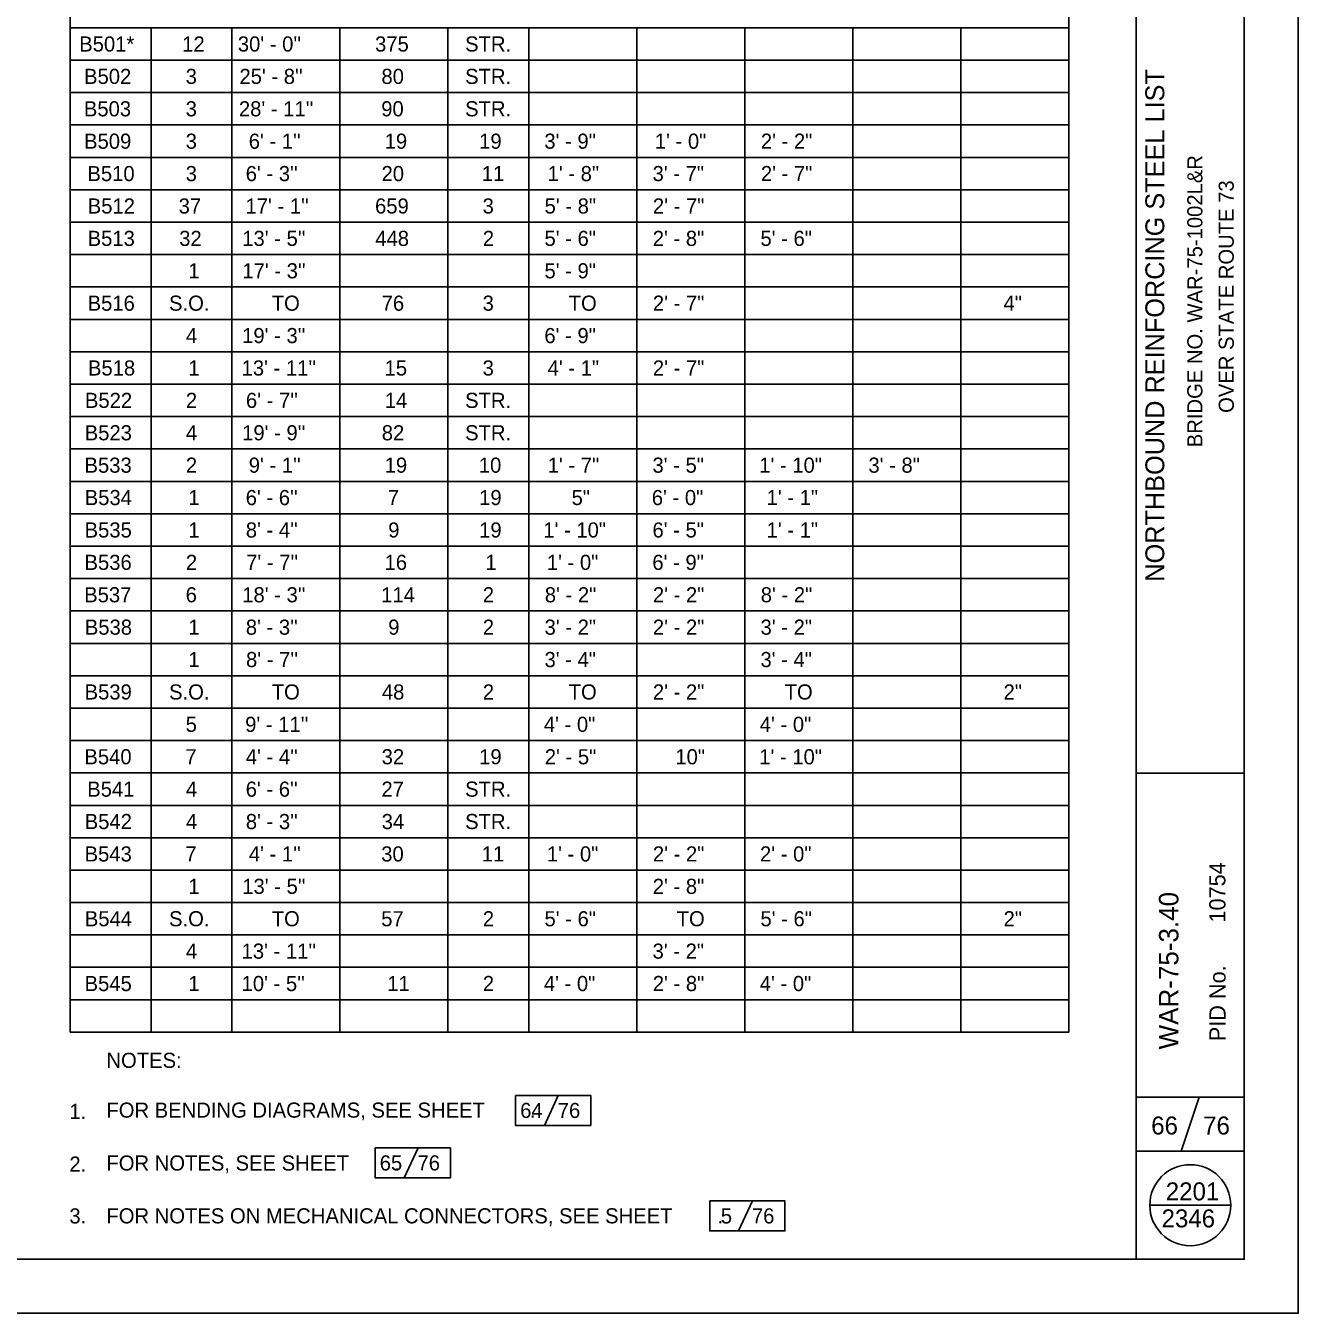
# Model space of a CAD drawing. Extents: x 1485751 to 1485785, y 230696.6 to 230718.6.
# Drawn here: x 1485773.25 to 1485785.03, y 230696.64 to 230708.56 of the extents above; entities that cross this region are included whole.
import ezdxf

# ---------------------------------------------------------------- set-up
doc = ezdxf.new("R2010")
doc.units = 0
for name, color, linetype in [('BR_P_Gen_Text', 7, 'Continuous'), ('BR_P_Sub_Text', 7, 'Continuous'), ('SH_Border', 7, 'Continuous'), ('SH_Cut_Line', 7, 'Continuous'), ('SH_Data', 7, 'Continuous'), ('TX_P_Misc', 7, 'Continuous')]:
    doc.layers.add(name, color=color, linetype=linetype)

msp = doc.modelspace()

# ---------------------------------------------------------------- linework, layer by layer
at = {"layer": 'BR_P_Gen_Text'}
for p, q in [((1485778.18, 230698.658), (1485778.052, 230698.38)), ((1485776.882, 230698.172), (1485776.753, 230697.894)), ((1485779.978, 230697.681), (1485779.85, 230697.403))]:
    msp.add_line(p, q, dxfattribs=at)
for points in [[(1485777.783, 230698.658), (1485778.48, 230698.658), (1485778.48, 230698.38), (1485777.783, 230698.38)], [(1485777.783, 230698.658), (1485778.48, 230698.658), (1485778.48, 230698.38), (1485777.783, 230698.38)], [(1485776.485, 230698.172), (1485777.181, 230698.172), (1485777.181, 230697.894), (1485776.485, 230697.894)], [(1485776.485, 230698.172), (1485777.181, 230698.172), (1485777.181, 230697.894), (1485776.485, 230697.894)], [(1485779.582, 230697.681), (1485780.278, 230697.681), (1485780.278, 230697.403), (1485779.582, 230697.403)], [(1485779.582, 230697.681), (1485780.278, 230697.681), (1485780.278, 230697.403), (1485779.582, 230697.403)]]:
    msp.add_lwpolyline(points, close=True, dxfattribs=at)
at = {"layer": 'SH_Border'}
for p, q in [((1485783.533, 230697.141), (1485783.533, 230718.141)), ((1485783.533, 230697.141), (1485783.533, 230718.141)), ((1485783.533, 230697.141), (1485783.533, 230718.141)), ((1485783.533, 230701.641), (1485784.533, 230701.641)), ((1485783.533, 230701.641), (1485784.533, 230701.641)), ((1485783.533, 230701.641), (1485784.533, 230701.641)), ((1485783.533, 230698.641), (1485784.533, 230698.641)), ((1485783.95, 230698.141), (1485784.116, 230698.641)), ((1485783.533, 230698.141), (1485784.533, 230698.141))]:
    msp.add_line(p, q, dxfattribs=at)
msp.add_lwpolyline([(1485753.033, 230718.141), (1485784.533, 230718.141), (1485784.533, 230697.141), (1485753.033, 230697.141)], close=True, dxfattribs=at)
at = {"layer": 'SH_Cut_Line'}
msp.add_lwpolyline([(1485751.033, 230718.641), (1485785.033, 230718.641), (1485785.033, 230696.641), (1485751.033, 230696.641)], close=True, dxfattribs=at)
at = {"layer": 'SH_Data'}
msp.add_line((1485783.658, 230697.641), (1485784.408, 230697.641), dxfattribs=at)
msp.add_line((1485783.658, 230697.641), (1485784.408, 230697.641), dxfattribs=at)
msp.add_line((1485783.658, 230697.641), (1485784.408, 230697.641), dxfattribs=at)
msp.add_circle((1485784.033, 230697.641), 0.375, dxfattribs=at)
at = {"layer": 'TX_P_Misc'}
for p, q in [((1485773.658, 230717.394), (1485773.658, 230699.244)), ((1485782.908, 230717.394), (1485782.908, 230699.244)), ((1485773.658, 230708.544), (1485782.908, 230708.544)), ((1485774.408, 230708.544), (1485774.408, 230699.244)), ((1485775.158, 230708.544), (1485775.158, 230699.244)), ((1485776.158, 230708.544), (1485776.158, 230699.244)), ((1485777.158, 230708.544), (1485777.158, 230699.244)), ((1485777.908, 230708.544), (1485777.908, 230699.244)), ((1485778.908, 230708.544), (1485778.908, 230699.244)), ((1485779.908, 230708.544), (1485779.908, 230699.244)), ((1485780.908, 230708.544), (1485780.908, 230699.244)), ((1485781.908, 230708.544), (1485781.908, 230699.244)), ((1485773.658, 230708.244), (1485782.908, 230708.244)), ((1485773.658, 230707.944), (1485782.908, 230707.944)), ((1485773.658, 230707.644), (1485782.908, 230707.644)), ((1485773.658, 230707.344), (1485782.908, 230707.344)), ((1485773.658, 230707.044), (1485782.908, 230707.044)), ((1485773.658, 230706.744), (1485782.908, 230706.744)), ((1485773.658, 230706.444), (1485782.908, 230706.444)), ((1485773.658, 230706.144), (1485782.908, 230706.144)), ((1485773.658, 230705.844), (1485782.908, 230705.844)), ((1485773.658, 230705.544), (1485782.908, 230705.544)), ((1485773.658, 230705.244), (1485782.908, 230705.244)), ((1485773.658, 230704.944), (1485782.908, 230704.944)), ((1485773.658, 230704.644), (1485782.908, 230704.644)), ((1485773.658, 230704.344), (1485782.908, 230704.344)), ((1485773.658, 230704.044), (1485782.908, 230704.044)), ((1485773.658, 230703.744), (1485782.908, 230703.744)), ((1485773.658, 230703.444), (1485782.908, 230703.444)), ((1485773.658, 230703.144), (1485782.908, 230703.144)), ((1485773.658, 230702.844), (1485782.908, 230702.844)), ((1485773.658, 230702.544), (1485782.908, 230702.544)), ((1485773.658, 230702.244), (1485782.908, 230702.244)), ((1485773.658, 230701.944), (1485782.908, 230701.944)), ((1485773.658, 230701.644), (1485782.908, 230701.644)), ((1485773.658, 230701.344), (1485782.908, 230701.344)), ((1485773.658, 230701.044), (1485782.908, 230701.044)), ((1485773.658, 230700.744), (1485782.908, 230700.744)), ((1485773.658, 230700.444), (1485782.908, 230700.444)), ((1485773.658, 230700.144), (1485782.908, 230700.144)), ((1485773.658, 230699.844), (1485782.908, 230699.844)), ((1485773.658, 230699.544), (1485782.908, 230699.544)), ((1485773.658, 230699.244), (1485782.908, 230699.244))]:
    msp.add_line(p, q, dxfattribs=at)

# ---------------------------------------------------------------- texts
at = {"layer": 'BR_P_Gen_Text'}
for s, p in [('64', (1485777.827, 230698.449)), ('76', (1485778.175, 230698.449)), ('65', (1485776.526, 230697.963)), ('76', (1485776.876, 230697.963)), ('5', (1485779.685, 230697.472)), ('76', (1485779.973, 230697.472))]:
    msp.add_text(s, height=0.14, dxfattribs=at).set_placement(p)
at = {"layer": 'BR_P_Sub_Text'}
msp.add_text('WAR-75-3.40', height=0.18, rotation=90, dxfattribs=at).set_placement((1485783.923, 230699.084))
at = {"layer": 'SH_Data'}
for s, height, p in [('     NORTHBOUND REINFORCING STEEL LIST    ', 0.175, (1485783.792, 230703.09)), ('BRIDGE NO. WAR-75-1002L&R', 0.14, (1485784.145, 230704.66)), ('OVER STATE ROUTE 73', 0.14, (1485784.436, 230704.978)), ('10754', 0.15, (1485784.358, 230700.259)), ('PID No.', 0.15, (1485784.36, 230699.16))]:
    msp.add_text(s, height=height, rotation=90, dxfattribs=at).set_placement(p)
for s, p in [('66', (1485783.671, 230698.296)), ('76', (1485784.152, 230698.296)), ('2201', (1485783.806, 230697.686)), ('2346', (1485783.767, 230697.436))]:
    msp.add_text(s, height=0.1666, dxfattribs=at).set_placement(p)
at = {"layer": 'TX_P_Misc'}
for s, p in [('B501*', (1485773.743, 230708.324)), ('12', (1485774.697, 230708.324)), ("30' - 0''", (1485775.212, 230708.324)), ('375', (1485776.483, 230708.324)), ('STR.', (1485777.317, 230708.324)), ('B502', (1485773.788, 230708.024)), ('3', (1485774.729, 230708.024)), ("25' - 8''", (1485775.227, 230708.024)), ('80', (1485776.542, 230708.024)), ('STR.', (1485777.317, 230708.024)), ('B503', (1485773.786, 230707.724)), ('3', (1485774.729, 230707.724)), ("28' - 11''", (1485775.222, 230707.724)), ('90', (1485776.54, 230707.724)), ('STR.', (1485777.317, 230707.724)), ('B509', (1485773.788, 230707.424)), ('3', (1485774.729, 230707.424)), ("6' - 1''", (1485775.313, 230707.424)), ('19', (1485776.572, 230707.424)), ('19', (1485777.447, 230707.424)), ('3\' - 9"', (1485778.051, 230707.424)), ('1\' - 0"', (1485779.074, 230707.424)), ('2\' - 2"', (1485780.056, 230707.424)), ('B510', (1485773.819, 230707.124)), ('3', (1485774.729, 230707.124)), ("6' - 3''", (1485775.285, 230707.124)), ('20', (1485776.543, 230707.124)), ('11', (1485777.471, 230707.124)), ('1\' - 8"', (1485778.081, 230707.124)), ('3\' - 7"', (1485779.053, 230707.124)), ('2\' - 7"', (1485780.056, 230707.124)), ('B512', (1485773.822, 230706.824)), ('37', (1485774.664, 230706.824)), ("17' - 1''", (1485775.283, 230706.824)), ('659', (1485776.483, 230706.824)), ('3', (1485777.479, 230706.824)), ('5\' - 8"', (1485778.053, 230706.824)), ('2\' - 7"', (1485779.056, 230706.824)), ('B513', (1485773.821, 230706.524)), ('32', (1485774.669, 230706.524)), ("13' - 5''", (1485775.253, 230706.524)), ('448', (1485776.485, 230706.524)), ('2', (1485777.481, 230706.524)), ('5\' - 6"', (1485778.052, 230706.524)), ('2\' - 8"', (1485779.055, 230706.524)), ('5\' - 6"', (1485780.052, 230706.524)), ('1', (1485774.754, 230706.224)), ("17' - 3''", (1485775.254, 230706.224)), ('5\' - 9"', (1485778.052, 230706.224)), ('B516', (1485773.821, 230705.924)), ('S.O.', (1485774.575, 230705.924)), ('TO', (1485775.526, 230705.924)), ('76', (1485776.544, 230705.924)), ('3', (1485777.479, 230705.924)), ('TO', (1485778.276, 230705.924)), ('2\' - 7"', (1485779.056, 230705.924)), (' 4"', (1485782.251, 230705.924)), ('4', (1485774.731, 230705.624)), ("19' - 3''", (1485775.252, 230705.624)), ('6\' - 9"', (1485778.051, 230705.624)), ('B518', (1485773.824, 230705.324)), ('1', (1485774.754, 230705.324)), ("13' - 11''", (1485775.247, 230705.324)), ('15', (1485776.571, 230705.324)), ('3', (1485777.479, 230705.324)), ('4\' - 1"', (1485778.081, 230705.324)), ('2\' - 7"', (1485779.056, 230705.324)), ('B522', (1485773.796, 230705.024)), ('2', (1485774.731, 230705.024)), ("6' - 7''", (1485775.287, 230705.024)), ('14', (1485776.573, 230705.024)), ('STR.', (1485777.317, 230705.024)), ('B523', (1485773.794, 230704.724)), ('4', (1485774.731, 230704.724)), ("19' - 9''", (1485775.252, 230704.724)), ('82', (1485776.545, 230704.724)), ('STR.', (1485777.317, 230704.724)), ('B533', (1485773.792, 230704.424)), ('2', (1485774.731, 230704.424)), ("9' - 1''", (1485775.313, 230704.424)), ('19', (1485776.572, 230704.424)), ('10', (1485777.444, 230704.424)), ('1\' - 7"', (1485778.082, 230704.424)), ('3\' - 5"', (1485779.052, 230704.424)), ('1\' - 10"', (1485780.041, 230704.424)), ('3\' - 8"', (1485781.052, 230704.424)), ('B534', (1485773.794, 230704.124)), ('1', (1485774.754, 230704.124)), ("6' - 6''", (1485775.285, 230704.124)), ('7', (1485776.601, 230704.124)), ('19', (1485777.447, 230704.124)), (' 5"', (1485778.251, 230704.124)), ('6\' - 0"', (1485779.046, 230704.124)), ('1\' - 1"', (1485780.109, 230704.124)), ('B535', (1485773.793, 230703.824)), ('1', (1485774.754, 230703.824)), ("8' - 4''", (1485775.286, 230703.824)), ('9', (1485776.605, 230703.824)), ('19', (1485777.447, 230703.824)), ('1\' - 10"', (1485778.041, 230703.824)), ('6\' - 5"', (1485779.052, 230703.824)), ('1\' - 1"', (1485780.109, 230703.824)), ('B536', (1485773.792, 230703.524)), ('2', (1485774.731, 230703.524)), ("7' - 7''", (1485775.289, 230703.524)), ('16', (1485776.571, 230703.524)), ('1', (1485777.504, 230703.524)), ('1\' - 0"', (1485778.074, 230703.524)), ('6\' - 9"', (1485779.051, 230703.524)), ('B537', (1485773.789, 230703.224)), ('6', (1485774.729, 230703.224)), ("18' - 3''", (1485775.253, 230703.224)), ('114', (1485776.54, 230703.224)), ('2', (1485777.481, 230703.224)), ('8\' - 2"', (1485778.055, 230703.224)), ('2\' - 2"', (1485779.056, 230703.224)), ('8\' - 2"', (1485780.055, 230703.224)), ('B538', (1485773.795, 230702.924)), ('1', (1485774.754, 230702.924)), ("8' - 3''", (1485775.286, 230702.924)), ('9', (1485776.605, 230702.924)), ('2', (1485777.481, 230702.924)), ('3\' - 2"', (1485778.053, 230702.924)), ('2\' - 2"', (1485779.056, 230702.924)), ('3\' - 2"', (1485780.053, 230702.924)), ('1', (1485774.754, 230702.624)), ("8' - 7''", (1485775.288, 230702.624)), ('3\' - 4"', (1485778.052, 230702.624)), ('3\' - 4"', (1485780.052, 230702.624)), ('B539', (1485773.793, 230702.324)), ('S.O.', (1485774.575, 230702.324)), ('TO', (1485775.526, 230702.324)), ('48', (1485776.546, 230702.324)), ('2', (1485777.481, 230702.324)), ('TO', (1485778.276, 230702.324)), ('2\' - 2"', (1485779.056, 230702.324)), ('TO', (1485780.276, 230702.324)), (' 2"', (1485782.252, 230702.324)), ('5', (1485774.729, 230702.024)), ("9' - 11''", (1485775.28, 230702.024)), ('4\' - 0"', (1485778.046, 230702.024)), ('4\' - 0"', (1485780.046, 230702.024)), ('B540', (1485773.791, 230701.724)), ('7', (1485774.726, 230701.724)), ("4' - 4''", (1485775.286, 230701.724)), ('32', (1485776.544, 230701.724)), ('19', (1485777.447, 230701.724)), ('2\' - 5"', (1485778.055, 230701.724)), (' 10"', (1485779.212, 230701.724)), ('1\' - 10"', (1485780.041, 230701.724)), ('B541', (1485773.817, 230701.424)), ('4', (1485774.731, 230701.424)), ("6' - 6''", (1485775.285, 230701.424)), ('27', (1485776.542, 230701.424)), ('STR.', (1485777.317, 230701.424)), ('B542', (1485773.794, 230701.124)), ('4', (1485774.731, 230701.124)), ("8' - 3''", (1485775.286, 230701.124)), ('34', (1485776.544, 230701.124)), ('STR.', (1485777.317, 230701.124)), ('B543', (1485773.793, 230700.824)), ('7', (1485774.726, 230700.824)), ("4' - 1''", (1485775.314, 230700.824)), ('30', (1485776.54, 230700.824)), ('11', (1485777.471, 230700.824)), ('1\' - 0"', (1485778.074, 230700.824)), ('2\' - 2"', (1485779.056, 230700.824)), ('2\' - 0"', (1485780.048, 230700.824)), ('1', (1485774.754, 230700.524)), ("13' - 5''", (1485775.253, 230700.524)), ('2\' - 8"', (1485779.055, 230700.524)), ('B544', (1485773.795, 230700.224)), ('S.O.', (1485774.575, 230700.224)), ('TO', (1485775.526, 230700.224)), ('57', (1485776.54, 230700.224)), ('2', (1485777.481, 230700.224)), ('5\' - 6"', (1485778.052, 230700.224)), ('TO', (1485779.276, 230700.224)), ('5\' - 6"', (1485780.052, 230700.224)), (' 2"', (1485782.252, 230700.224)), ('4', (1485774.731, 230699.924)), ("13' - 11''", (1485775.247, 230699.924)), ('3\' - 2"', (1485779.053, 230699.924)), ('B545', (1485773.793, 230699.624)), ('1', (1485774.754, 230699.624)), ("10' - 5''", (1485775.247, 230699.624)), ('11', (1485776.596, 230699.624)), ('2', (1485777.481, 230699.624)), ('4\' - 0"', (1485778.046, 230699.624)), ('2\' - 8"', (1485779.055, 230699.624)), ('4\' - 0"', (1485780.046, 230699.624)), ('NOTES:', (1485773.995, 230698.913)), ('1.', (1485773.652, 230698.44)), ('FOR BENDING DIAGRAMS, SEE SHEET        .', (1485773.995, 230698.452)), ('2.', (1485773.652, 230697.952)), ('FOR NOTES, SEE SHEET        .', (1485773.995, 230697.962)), ('3.', (1485773.652, 230697.472)), ('FOR NOTES ON MECHANICAL CONNECTORS, SEE SHEET        .', (1485773.995, 230697.473))]:
    msp.add_text(s, height=0.14, dxfattribs=at).set_placement(p)

doc.saveas('drawing.dxf')
